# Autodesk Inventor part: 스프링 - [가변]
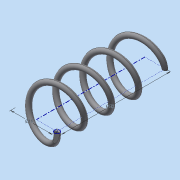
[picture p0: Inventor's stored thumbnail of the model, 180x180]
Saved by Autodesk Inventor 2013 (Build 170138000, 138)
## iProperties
Created: 2015-09
Part Number: 스프링 - [가변]
Material: 일반
Document SubType Name: Modeling
Designer: Administrator
Density: 1 g/cm^3
Mass: 0.625201 g
Surface Area: 12.7475 cm^2
Volume: 0.625201 cm^3
Author: Administrator
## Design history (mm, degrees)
sketch "스케치1"
  geometry: L1 (0, 0)-(8, 0); L2 (8, 0)-(8, 42); L3 (8, 42)-(0, 42); L4 (0, 42)-(0, 0); C1 r 1 at (8, 0)
  constraints: 8 end point, 2 parallel, 1 centre point, 1 coincident, 1 horizontal, 1 perpendicular
  dimensions: "d0" = 2 diameter of C1; "d2" = 42 distance between parallel lines of L1 L3 (derived); "d3" = 16 diameter of L2 L4
feature "코일1" pitch "d4" = 10; turns "d6" = 4; dims "d5" = 42 (= d2), "d7" = 0, angle "d8" = 90 deg, angle "d9" = 90 deg, "d10" = 0, "d11" = 0
sketch "스케치2"
  geometry: L1 (-9, 0)-(-7, 0) reference; L2 (-9, 0)-(-7, 0) reference; 1 further point
  constraints: 2 horizontal alignment
extrude "돌출1" cut sketch "스케치2" distance "d12" = 10; taper "d13" = 0 deg
node "작업 평면1"
sketch "스케치3"
  geometry: L1 (2, 0)-(0, 0) reference; 1 further point
  constraints: 1 horizontal alignment
extrude "돌출2" cut sketch "스케치3" distance "d14" = 10; taper "d15" = 0 deg
node "솔리드1"
node "절단 모서리 투영1"
node "절단 모서리 투영2"
node "절단 모서리 투영3"
